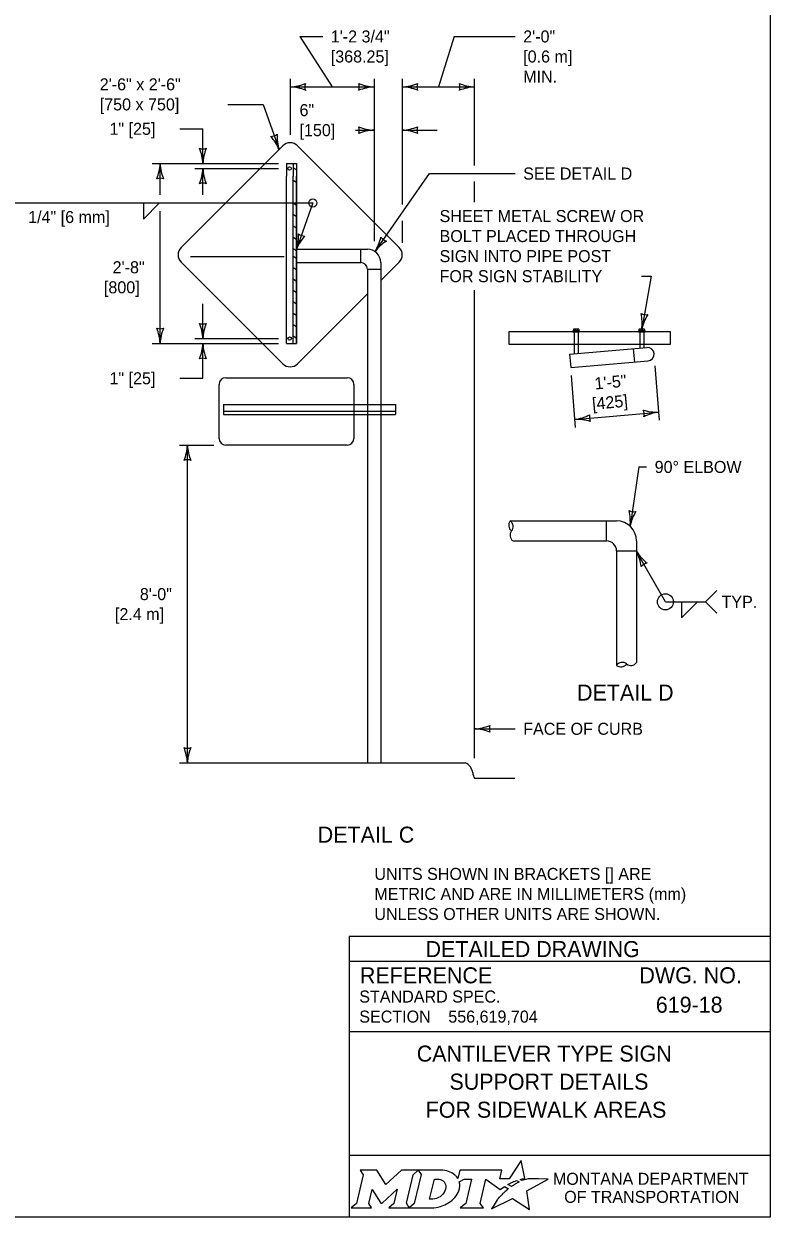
# Model space of a CAD drawing. Extents: x 49991.4 to 50021, y 49987.6 to 50011.4.
# Drawn here: x 50013.03 to 50016.75, y 49987.8 to 49993.75 of the extents above; entities that cross this region are included whole.
import ezdxf

# ---------------------------------------------------------------- set-up
doc = ezdxf.new("R2010")
doc.units = 0
for name, color, linetype in [('Default', 7, 'Continuous'), ('Level 1', 7, 'Continuous'), ('Level 2', 7, 'Continuous'), ('Level 3', 7, 'Continuous'), ('Level 4', 7, 'Continuous'), ('Level 5', 7, 'Continuous')]:
    doc.layers.add(name, color=color, linetype=linetype)

msp = doc.modelspace()

# ---------------------------------------------------------------- linework, layer by layer
at = {"layer": 'Default'}
for points in [[(50015.5126, 49987.9811), (50015.5023, 49987.9867), (50015.5139, 49987.9895), (50015.5255, 49987.9915), (50015.5081, 49988.0816), (50015.4486, 49987.9903), (50015.4013, 49987.9896), (50015.4116, 49988.0337), (50015.2024, 49988.0338), (50015.1923, 49987.9913), (50015.1865, 49987.9996)], [(50014.7056, 49988.0338), (50014.7197, 49988.0104), (50014.6862, 49987.8671), (50014.6605, 49987.8446), (50014.7621, 49987.8446), (50014.7486, 49987.8674), (50014.7648, 49987.9375), (50014.8085, 49987.8685), (50014.8138, 49987.8685), (50014.8889, 49987.938), (50014.8725, 49987.8669), (50014.8478, 49987.8449), (50014.9494, 49987.8449), (50014.9356, 49987.8682), (50014.9688, 49988.0106)], [(50014.9688, 49988.0106), (50014.9941, 49988.0338), (50014.9117, 49988.0338), (50014.8321, 49987.9608), (50014.7876, 49988.0335), (50014.7056, 49988.0338)], [(50015.1077, 49988.0338), (50014.9941, 49988.0338), (50015.0088, 49988.0109), (50014.9749, 49987.8671), (50014.9494, 49987.8449), (50015.06, 49987.8449)], [(50015.1317, 49987.9471), (50015.1305, 49987.939), (50015.1273, 49987.9297), (50015.1231, 49987.9215), (50015.1175, 49987.914), (50015.111, 49987.9071), (50015.1031, 49987.9008), (50015.0948, 49987.8961), (50015.0857, 49987.8922), (50015.0766, 49987.8899), (50015.0674, 49987.889), (50015.0515, 49987.889), (50015.0751, 49987.989), (50015.0911, 49987.989), (50015.0987, 49987.9884), (50015.1063, 49987.9865), (50015.1129, 49987.9835), (50015.119, 49987.9793), (50015.1238, 49987.9743), (50015.1275, 49987.9683), (50015.1302, 49987.9621), (50015.1318, 49987.9547), (50015.1318, 49987.9517), (50015.1317, 49987.9471)], [(50015.1991, 49987.9747), (50015.2237, 49987.9878), (50015.2606, 49987.9878), (50015.232, 49987.8673), (50015.2045, 49987.8446), (50015.3207, 49987.8446), (50015.3037, 49987.8675), (50015.3319, 49987.9877), (50015.4032, 49987.936), (50015.4243, 49987.9511), (50015.444, 49987.9402)], [(50015.3882, 49987.8843), (50015.3729, 49987.8599), (50015.3682, 49987.8524), (50015.3624, 49987.8438), (50015.3601, 49987.8395), (50015.4654, 49987.8926), (50015.5493, 49987.8375), (50015.5362, 49987.9302), (50015.6431, 49987.9886), (50015.5938, 49987.9894), (50015.5637, 49987.9898), (50015.5429, 49987.9901), (50015.5361, 49987.9886), (50015.5312, 49987.9874), (50015.5228, 49987.9851), (50015.5126, 49987.9811)], [(50015.4622, 49987.9535), (50015.4598, 49987.9518), (50015.4415, 49987.9614), (50015.4518, 49987.9671), (50015.4559, 49987.9693), (50015.4645, 49987.9733), (50015.4702, 49987.9759), (50015.4781, 49987.9789), (50015.4854, 49987.9816), (50015.4972, 49987.9742), (50015.4932, 49987.9721), (50015.4886, 49987.9696), (50015.4844, 49987.9674), (50015.4794, 49987.9645), (50015.4775, 49987.9634), (50015.4748, 49987.9618), (50015.4723, 49987.9604), (50015.47, 49987.9588), (50015.4674, 49987.957), (50015.4647, 49987.9552), (50015.4622, 49987.9535)], [(50015.4021, 49987.9004), (50015.4021, 49987.9004)], [(50015.1057, 49987.8522), (50015.1141, 49987.8548), (50015.1271, 49987.8602), (50015.1475, 49987.8712)]]:
    msp.add_lwpolyline(points, dxfattribs=at)
for centre, radius, start, end in [((50015.1308, 49987.9554), 0.0709, 339.53292, 15.85821), ((50015.0868, 49987.9727), 0.1183, 300.91025, 339.13831)]:
    msp.add_arc(centre, radius, start, end, dxfattribs=at)
for centre, major_axis, ratio, start_param, end_param in [((50015.1056, 49987.9864), (0.0834, -0.0037), 0.568097, 0.61298, 1.570796), ((50015.1612, 49987.9937), (0.0361, -0.0295), 0.469099, 1.225588, 1.570796), ((50015.3952, 49987.8923), (-0.00694, -0.00806), 0.008222, 0, 3.137361), ((50015.4119, 49987.9106), (-0.0098, -0.0102), 0.016458, 3.141593, 6.279097), ((50015.4329, 49987.9305), (-0.0112, -0.0097), 0.021651, 3.157348, 6.283185), ((50015.0603, 49987.9932), (0, 0.1484), 0.987302, 3.139398, 3.456847)]:
    msp.add_ellipse(centre, major_axis=major_axis, ratio=ratio, start_param=start_param, end_param=end_param, dxfattribs=at)
at = {"layer": 'Level 1'}
for p, q in [((50014.3194, 49993.1447), (50013.8116, 49992.6368)), ((50014.8998, 49992.6368), (50014.3919, 49993.1447)), ((50014.3366, 49993.0555), (50014.3865, 49993.0555)), ((50014.3366, 49993.0555), (50014.3366, 49992.9931)), ((50014.3698, 49993.0555), (50014.3698, 49992.9931)), ((50014.3849, 49993.0243), (50014.3713, 49993.0334)), ((50014.3865, 49993.0555), (50014.3865, 49992.9931)), ((50014.3865, 49993.0555), (50014.3865, 49992.1577)), ((50014.3366, 49992.5992), (50014.3366, 49992.9931)), ((50014.3366, 49992.983), (50014.3366, 49992.9931)), ((50014.3698, 49992.9682), (50014.3698, 49992.9931)), ((50014.3698, 49992.5992), (50014.3698, 49992.9682)), ((50014.3865, 49992.9604), (50014.3704, 49992.9715)), ((50014.3865, 49992.983), (50014.3865, 49992.9931)), ((50014.3865, 49992.5992), (50014.3865, 49992.983)), ((50014.3865, 49992.8468), (50014.3704, 49992.8577)), ((50014.3865, 49992.79), (50014.3704, 49992.8009)), ((50014.3865, 49992.7331), (50014.3704, 49992.744)), ((50014.3865, 49992.6762), (50014.3704, 49992.6872)), ((50014.3865, 49992.6193), (50014.3704, 49992.6303)), ((50014.3865, 49992.6283), (50014.7407, 49992.6283)), ((50014.7074, 49992.5618), (50014.7074, 49992.6283)), ((50013.8116, 49992.5642), (50014.3194, 49992.0564)), ((50014.3366, 49992.1577), (50014.3366, 49992.5992)), ((50014.3698, 49992.1577), (50014.3698, 49992.5992)), ((50014.3865, 49992.5815), (50014.3704, 49992.5925)), ((50014.3865, 49992.1577), (50014.3865, 49992.5992)), ((50014.3865, 49992.5618), (50014.7074, 49992.5618)), ((50014.8072, 49992.4716), (50014.8998, 49992.5642)), ((50014.8072, 49992.5618), (50014.8072, 49990.0653)), ((50014.3865, 49992.5246), (50014.3704, 49992.5355)), ((50014.7407, 49992.5285), (50014.7407, 49990.0653)), ((50014.7407, 49992.5285), (50014.8071, 49992.5285)), ((50014.3865, 49992.4677), (50014.3704, 49992.4786)), ((50014.3865, 49992.4109), (50014.3704, 49992.4218)), ((50014.3865, 49992.354), (50014.3704, 49992.3649)), ((50014.3919, 49992.0564), (50014.7407, 49992.4051)), ((50014.3865, 49992.2972), (50014.3704, 49992.3081)), ((50014.3865, 49992.2403), (50014.3704, 49992.2512)), ((50014.3865, 49992.1834), (50014.3704, 49992.1943)), ((50015.7685, 49992.2268), (50015.7685, 49992.2207)), ((50015.7936, 49992.2294), (50015.771, 49992.2294)), ((50015.7937, 49992.2294), (50015.771, 49992.2294)), ((50015.7777, 49992.2294), (50015.7777, 49992.2207)), ((50015.7871, 49992.2294), (50015.7871, 49992.2207)), ((50015.7962, 49992.2268), (50015.7962, 49992.2207)), ((50016.0956, 49992.2268), (50016.0956, 49992.2207)), ((50016.1208, 49992.2294), (50016.0979, 49992.2294)), ((50016.1211, 49992.2294), (50016.0986, 49992.2294)), ((50016.1048, 49992.2294), (50016.1048, 49992.2207)), ((50016.1141, 49992.2294), (50016.1141, 49992.2207)), ((50016.1233, 49992.2268), (50016.1233, 49992.2207)), ((50014.3366, 49992.1577), (50014.3865, 49992.1577)), ((50015.7494, 49992.1037), (50016.1355, 49992.1374)), ((50015.7725, 49992.1543), (50015.7725, 49992.1057)), ((50015.7925, 49992.1543), (50015.7925, 49992.1075)), ((50016.075, 49992.0654), (50016.0692, 49992.1316)), ((50016.0995, 49992.1543), (50016.0995, 49992.1343)), ((50016.1195, 49992.1543), (50016.1195, 49992.136)), ((50015.7494, 49992.1037), (50015.7553, 49992.0374)), ((50015.7553, 49992.0374), (50016.1411, 49992.0712)), ((50015.4532, 49991.2725), (50015.9839, 49991.2725)), ((50015.934, 49991.1727), (50015.934, 49991.2725)), ((50015.4673, 49991.1725), (50015.934, 49991.1727)), ((50015.9839, 49991.1228), (50015.9837, 49990.5516)), ((50015.9839, 49991.1228), (50016.0836, 49991.1229)), ((50016.0836, 49991.1727), (50016.0837, 49990.5658)), ((50013.8027, 49990.0653), (50015.1731, 49990.0653)), ((50015.1731, 49990.0653), (50015.2293, 49990.0653)), ((50015.2759, 49989.9882), (50015.4759, 49989.9882))]:
    msp.add_line(p, q, dxfattribs=at)
for points in [[(49999.3835, 49998.9992), (50016.7501, 49998.9992), (50016.7501, 49987.7988), (49999.3835, 49987.7988)], [(50016.2532, 49992.1543), (50016.2532, 49992.216), (50015.4457, 49992.216), (50015.4457, 49992.1543)], [(50015.7989, 49992.2158), (50015.7989, 49992.2205), (50015.7661, 49992.2205), (50015.7661, 49992.2158)], [(50016.126, 49992.2158), (50016.126, 49992.2205), (50016.0931, 49992.2205), (50016.0931, 49992.2158)]]:
    msp.add_lwpolyline(points, close=True, dxfattribs=at)
for centre in [(50014.353, 49993.031), (50014.353, 49992.1822)]:
    msp.add_circle(centre, 0.00843, dxfattribs=at)
for centre, radius, start, end in [((50014.3557, 49993.1084), 0.0513, 45.00008, 134.99993), ((50013.8478, 49992.6005), 0.0513, 134.99993, 225.00008), ((50014.7407, 49992.5618), 0.0665, 0, 90), ((50014.8635, 49992.6005), 0.0513, 314.99993, 45.00008), ((50014.7074, 49992.5285), 0.0333, 0, 90), ((50015.7711, 49992.2268), 0.00257, 90, 180), ((50015.7752, 49992.2268), 0.00257, 0, 90), ((50015.7804, 49992.2268), 0.00257, 90, 180), ((50015.7844, 49992.2268), 0.00257, 0, 90), ((50015.7896, 49992.2268), 0.00257, 90, 180), ((50015.7936, 49992.2268), 0.00257, 0, 90), ((50016.0982, 49992.2268), 0.00257, 97.71849, 180), ((50016.1023, 49992.2268), 0.00257, 360, 82.28151), ((50016.1074, 49992.2268), 0.00257, 97.71849, 180), ((50016.1115, 49992.2268), 0.00257, 0, 82.28151), ((50016.1167, 49992.2268), 0.00257, 97.71849, 180), ((50016.1207, 49992.2268), 0.00257, 0, 82.28151), ((50016.1383, 49992.1043), 0.0332, 274.91306, 94.91306), ((50014.3557, 49992.0927), 0.0513, 225.00007, 314.99993), ((50015.4816, 49991.2506), 0.0359, 142.47417, 231.88124), ((50015.4344, 49991.2442), 0.034, 320.09958, 55.51698), ((50015.9839, 49991.1727), 0.0998, 0, 90), ((50015.4866, 49991.2006), 0.034, 140.09958, 235.51698), ((50015.4816, 49991.2506), 0.0359, 232.45136, 233.33014), ((50015.934, 49991.1228), 0.0499, 0, 90), ((50016.012, 49990.5328), 0.034, 50.09958, 145.51698), ((50016.0556, 49990.585), 0.034, 230.09958, 325.51698), ((50015.2056, 49990.0091), 0.061, 5.91179, 67.14905)]:
    msp.add_arc(centre, radius, start, end, dxfattribs=at)
for centre, major_axis, ratio, start_param, end_param in [((50016.0061, 49990.5807), (-0.0223, -0.0291), 0.979506, 0, 1.560448), ((50015.3269, 49990.0217), (-0.0223, -0.0568), 0.999596, 5.190058, 5.66782)]:
    msp.add_ellipse(centre, major_axis=major_axis, ratio=ratio, start_param=start_param, end_param=end_param, dxfattribs=at)
at = {"layer": 'Level 3'}
for p, q in [((50014.4034, 49993.6897), (50014.5647, 49993.4377)), ((50014.4034, 49993.6897), (50014.5181, 49993.6897)), ((50015.1745, 49993.6897), (50015.0954, 49993.4377)), ((50015.1745, 49993.6897), (50015.4781, 49993.6897)), ((50014.3554, 49993.4777), (50014.3554, 49993.1997)), ((50014.3554, 49993.4377), (50014.7739, 49993.4377)), ((50014.7739, 49993.4777), (50014.7739, 49992.6683)), ((50014.9148, 49993.4777), (50014.9148, 49992.8506)), ((50014.9148, 49993.4377), (50015.276, 49993.4377)), ((50015.276, 49993.0459), (50015.276, 49993.4777)), ((50014.0441, 49993.3508), (50014.2205, 49993.3508)), ((50014.2205, 49993.3508), (50014.2999, 49993.1252)), ((50013.8051, 49993.2289), (50013.9204, 49993.2289)), ((50013.9204, 49993.0555), (50013.9204, 49993.2289)), ((50014.6817, 49993.2222), (50014.7739, 49993.2222)), ((50014.9148, 49993.2222), (50015.0882, 49993.2222)), ((50013.6668, 49993.0555), (50014.2966, 49993.0555)), ((50013.7068, 49992.8988), (50013.7068, 49993.0555)), ((50013.8804, 49993.031), (50014.2966, 49993.031)), ((50013.9204, 49992.8988), (50013.9204, 49993.031)), ((50014.7788, 49992.6162), (50015.0515, 49993.0059)), ((50015.0515, 49993.0059), (50015.2693, 49993.0059)), ((50015.2693, 49993.0059), (50015.4781, 49993.0059)), ((50015.276, 49992.8637), (50015.276, 49992.9659)), ((50012.9528, 49992.8588), (50014.1183, 49992.8588)), ((50013.6233, 49992.8588), (50013.6233, 49992.7788)), ((50013.6233, 49992.7788), (50013.7033, 49992.8588)), ((50014.1183, 49992.8588), (50014.2839, 49992.8588)), ((50014.2839, 49992.8588), (50014.4687, 49992.8588)), ((50014.4687, 49992.8588), (50014.3865, 49992.6283)), ((50013.7068, 49992.1577), (50013.7068, 49992.8188)), ((50014.9148, 49992.7706), (50014.9148, 49992.6605)), ((50016.1087, 49992.4937), (50016.1566, 49992.4937)), ((50016.1566, 49992.4937), (50016.1096, 49992.2298)), ((50015.276, 49990.0882), (50015.276, 49992.4237)), ((50013.9204, 49992.1822), (50013.9204, 49992.3556)), ((50013.6668, 49992.1577), (50014.2966, 49992.1577)), ((50013.8804, 49992.1822), (50014.2966, 49992.1822)), ((50013.9204, 49991.9843), (50013.9204, 49992.1577)), ((50016.1977, 49991.776), (50016.1766, 49992.047)), ((50013.8051, 49991.9843), (50013.9204, 49991.9843)), ((50015.7788, 49991.7393), (50015.7588, 49991.9975)), ((50015.7753, 49991.7791), (50016.1942, 49991.8158)), ((50013.8027, 49991.6507), (50013.9746, 49991.6507)), ((50013.8427, 49990.0653), (50013.8427, 49991.6507)), ((50016.0955, 49991.5417), (50016.0515, 49991.246)), ((50016.0955, 49991.5417), (50016.1341, 49991.5417)), ((50016.2277, 49990.8688), (50016.0837, 49991.1193)), ((50016.4277, 49990.8688), (50016.4843, 49990.9254)), ((50016.2277, 49990.8688), (50016.4277, 49990.8688)), ((50016.3077, 49990.8688), (50016.3077, 49990.7888)), ((50016.3077, 49990.7888), (50016.3877, 49990.8688)), ((50016.4277, 49990.8688), (50016.4843, 49990.8122)), ((50015.276, 49990.2353), (50015.4781, 49990.2353))]:
    msp.add_line(p, q, dxfattribs=at)
for centre, radius in [((50014.4687, 49992.8588), 0.0201), ((50016.2277, 49990.8688), 0.04)]:
    msp.add_circle(centre, radius, dxfattribs=at)
for centre, radius, start, end in [((50014.3439, 49993.6705), 0.233, 272.82731, 292.07716), ((50014.3463, 49993.2156), 0.2223, 67.45601, 87.63952), ((50014.4836, 49993.4377), 0.0548, 162.13882, 197.86118), ((50014.7831, 49993.6599), 0.2223, 247.45601, 267.63952), ((50014.6457, 49993.4377), 0.0548, 342.13882, 17.86118), ((50014.7854, 49993.205), 0.233, 92.82731, 112.07716), ((50014.9033, 49993.6705), 0.233, 272.82731, 292.07716), ((50014.9057, 49993.2156), 0.2223, 67.45601, 87.63952), ((50015.043, 49993.4377), 0.0548, 162.13882, 197.86118), ((50015.2851, 49993.6599), 0.2223, 247.45601, 267.63952), ((50015.1477, 49993.4377), 0.0548, 342.13882, 17.86118), ((50015.2874, 49993.205), 0.233, 92.82731, 112.07716), ((50014.2573, 49993.2461), 0.0548, 271.54113, 307.2635), ((50014.5125, 49993.1904), 0.2223, 176.85833, 197.04183), ((50014.7831, 49993.4443), 0.2223, 247.45601, 267.63952), ((50014.6457, 49993.2222), 0.0548, 342.13882, 17.86118), ((50014.7854, 49992.9895), 0.233, 92.82731, 112.07716), ((50014.9033, 49993.4549), 0.233, 272.82731, 292.07716), ((50014.9057, 49993.0001), 0.2223, 67.45601, 87.63952), ((50015.043, 49993.2222), 0.0548, 162.13882, 197.86118), ((50014.0842, 49993.0371), 0.233, 22.22963, 41.47948), ((50013.9204, 49993.1837), 0.0548, 252.13882, 287.86118), ((50013.6877, 49993.044), 0.233, 2.82731, 22.07716), ((50014.1425, 49993.0463), 0.2223, 157.45601, 177.63952), ((50013.4847, 49993.0647), 0.2223, 337.45601, 357.63952), ((50013.9395, 49993.067), 0.233, 182.82731, 202.07716), ((50013.6983, 49993.0402), 0.2223, 337.45601, 357.63952), ((50014.1531, 49993.0425), 0.233, 182.82731, 202.07716), ((50013.7068, 49992.9273), 0.0548, 72.13882, 107.86118), ((50013.9204, 49992.9028), 0.0548, 72.13882, 107.86118), ((50014.1644, 49992.6986), 0.233, 342.44053, 1.69038), ((50014.5915, 49992.5423), 0.2223, 137.06923, 157.25274), ((50014.4312, 49992.7485), 0.0548, 231.75204, 267.4744), ((50014.5816, 49992.7403), 0.233, 327.84304, 347.09289), ((50014.9556, 49992.4814), 0.2223, 122.47174, 142.65525), ((50014.8523, 49992.7213), 0.0548, 217.15455, 252.87691), ((50016.1321, 49992.3564), 0.0551, 242.04763, 277.76999), ((50015.877, 49992.259), 0.2344, 352.73612, 11.98597), ((50013.9204, 49992.3104), 0.0548, 252.13882, 287.86118), ((50013.6877, 49992.1707), 0.233, 2.82731, 22.07716), ((50014.1425, 49992.173), 0.2223, 157.45601, 177.63952), ((50016.328, 49992.1811), 0.2237, 147.36482, 167.54833), ((50013.7068, 49992.2859), 0.0548, 252.13882, 287.86118), ((50013.4741, 49992.1462), 0.233, 2.82731, 22.07716), ((50013.9289, 49992.1485), 0.2223, 157.45601, 177.63952), ((50013.6983, 49992.1669), 0.2223, 337.45601, 357.63952), ((50014.1531, 49992.1692), 0.233, 182.82731, 202.07716), ((50013.9204, 49992.0295), 0.0548, 72.13882, 107.86118), ((50015.7435, 49992.0099), 0.233, 277.84279, 297.09264), ((50015.7856, 49991.557), 0.2223, 72.47149, 92.655), ((50015.9031, 49991.7903), 0.0548, 167.1543, 202.87666), ((50016.1839, 49992.0379), 0.2223, 252.47149, 272.655), ((50016.0665, 49991.8046), 0.0548, 347.1543, 22.87666), ((50016.226, 49991.585), 0.233, 97.84279, 117.09264), ((50013.6206, 49991.6599), 0.2223, 337.45601, 357.63952), ((50014.0754, 49991.6622), 0.233, 182.82731, 202.07716), ((50013.8427, 49991.5225), 0.0548, 72.13882, 107.86118), ((50016.0704, 49991.3728), 0.0548, 243.67431, 279.39667), ((50015.8197, 49991.2689), 0.233, 354.3628, 13.61265), ((50016.2699, 49991.2042), 0.2223, 148.9915, 169.17501), ((50015.8866, 49991.0165), 0.2223, 7.35104, 27.53455), ((50016.2798, 49991.2452), 0.233, 212.72234, 231.97219), ((50016.1476, 49991.0081), 0.0548, 102.03385, 137.75621), ((50015.2645, 49990.468), 0.233, 272.82731, 292.07716), ((50015.2668, 49990.0132), 0.2223, 67.45601, 87.63952), ((50015.4042, 49990.2353), 0.0548, 162.13882, 197.86118), ((50013.8427, 49990.1935), 0.0548, 252.13882, 287.86118), ((50013.61, 49990.0538), 0.233, 2.82731, 22.07716), ((50014.0648, 49990.0561), 0.2223, 157.45601, 177.63952)]:
    msp.add_arc(centre, radius, start, end, dxfattribs=at)
at = {"layer": 'Level 4'}
for p, q in [((50015.7725, 49992.2158), (50015.7725, 49992.1543)), ((50015.7925, 49992.2158), (50015.7925, 49992.1543)), ((50016.0995, 49992.2158), (50016.0995, 49992.1543)), ((50016.1195, 49992.2158), (50016.1195, 49992.1543)), ((50014.0009, 49991.6844), (50014.0009, 49991.9536)), ((50014.0346, 49991.9872), (50014.6401, 49991.9872)), ((50014.6738, 49991.9536), (50014.6738, 49991.6844)), ((50014.0229, 49991.8541), (50014.0229, 49991.8041)), ((50014.0229, 49991.8541), (50014.8805, 49991.8541)), ((50014.8805, 49991.8541), (50014.8805, 49991.8041)), ((50014.0229, 49991.8209), (50014.8805, 49991.8209)), ((50014.0229, 49991.8041), (50014.8805, 49991.8041)), ((50014.6401, 49991.6507), (50014.0346, 49991.6507))]:
    msp.add_line(p, q, dxfattribs=at)
for centre, start, end in [((50014.0345, 49991.9536), 90, 180), ((50014.6401, 49991.9536), 0, 90), ((50014.6401, 49991.6844), 270, 0)]:
    msp.add_arc(centre, 0.0336, start, end, dxfattribs=at)
msp.add_ellipse((50014.0346, 49991.6844), major_axis=(-0.0337, 0), ratio=0.998923, start_param=0, end_param=1.570796, dxfattribs=at)
at = {"layer": 'Level 5'}
for p, q in [((50013.8575, 49992.5918), (50014.3255, 49992.5918)), ((50016.7501, 49989.1988), (50014.6501, 49989.1988)), ((50014.6501, 49989.1988), (50014.6501, 49987.7988)), ((50016.7501, 49989.0738), (50014.6501, 49989.0738)), ((50016.3862, 49988.8587), (50016.3862, 49988.8587)), ((50015.1444, 49988.7993), (50015.1444, 49988.7993)), ((50016.7501, 49988.7238), (50014.6501, 49988.7238)), ((50015.7001, 49988.4747), (50015.7001, 49988.4747)), ((50016.7501, 49988.1057), (50014.6501, 49988.1057))]:
    msp.add_line(p, q, dxfattribs=at)

# ---------------------------------------------------------------- texts
at = {"layer": 'Default'}
for s, p in [('MONTANA DEPARTMENT', (50015.6663, 49987.96)), ('OF TRANSPORTATION', (50015.7225, 49987.87))]:
    msp.add_text(s, height=0.06, dxfattribs=at).set_placement(p)
at = {"layer": 'Level 2'}
for s, height, p in [('1\'-2 3/4"', 0.06, (50014.5581, 49993.6597)), ('2\'-0"', 0.06, (50015.5181, 49993.6597)), ('[368.25]', 0.06, (50014.5581, 49993.5597)), ('[0.6 m]', 0.06, (50015.5181, 49993.5597)), ('MIN.', 0.06, (50015.5181, 49993.4597)), ('2\'-6" x 2\'-6"', 0.06, (50013.4055, 49993.4208)), ('[750 x 750]', 0.06, (50013.4055, 49993.3208)), ('6"', 0.06, (50014.4022, 49993.2922)), ('1" [25]', 0.06, (50013.454, 49993.1989)), ('[150]', 0.06, (50014.4022, 49993.1922)), ('SEE DETAIL D', 0.06, (50015.5181, 49992.9759)), ('1/4" [6 mm]', 0.06, (50013.0483, 49992.7588)), ('SHEET METAL SCREW OR', 0.06, (50015.1009, 49992.7637)), ('BOLT PLACED THROUGH', 0.06, (50015.1009, 49992.6637)), ('SIGN INTO PIPE POST', 0.06, (50015.1009, 49992.5637)), ('2\'-8"', 0.06, (50013.4699, 49992.5082)), ('FOR SIGN STABILITY', 0.06, (50015.1009, 49992.4637)), ('[800]', 0.06, (50013.4264, 49992.4082)), ('1" [25]', 0.06, (50013.454, 49991.9543)), ('90° ELBOW', 0.06, (50016.1741, 49991.5117)), ('8\'-0"', 0.06, (50013.6057, 49990.8774)), ('TYP.', 0.06, (50016.5077, 49990.8388)), ('[2.4 m]', 0.06, (50013.4813, 49990.7774)), ('DETAIL D', 0.08, (50015.7869, 49990.3761)), ('FACE OF CURB', 0.06, (50015.5181, 49990.2053)), ('DETAIL C', 0.08, (50014.4931, 49989.6672)), ('UNITS SHOWN IN BRACKETS [] ARE ', 0.06, (50014.7757, 49989.4813)), ('METRIC AND ARE IN MILLIMETERS (mm) ', 0.06, (50014.7757, 49989.3813)), ('UNLESS OTHER UNITS ARE SHOWN.', 0.06, (50014.7757, 49989.2813)), ('619-18', 0.08, (50016.1798, 49988.8187)), ('556,619,704', 0.06, (50015.1444, 49988.7693)), ('CANTILEVER TYPE SIGN', 0.08, (50014.987, 49988.5747)), ('SUPPORT DETAILS', 0.08, (50015.1504, 49988.4347)), ('FOR SIDEWALK AREAS', 0.08, (50015.0316, 49988.2947))]:
    msp.add_text(s, height=height, dxfattribs=at).set_placement(p)
for s, p in [('1\'-5"', (50015.877, 49991.9279)), ('[425]', (50015.8646, 49991.8264))]:
    msp.add_text(s, height=0.06, rotation=5.36424, dxfattribs=at).set_placement(p)
at = {"layer": 'Level 5'}
for s, height, p in [('DETAILED DRAWING', 0.0799, (50015.0311, 49989.0963)), ('REFERENCE', 0.08, (50014.7037, 49988.9654)), ('DWG. NO.', 0.08, (50016.0979, 49988.9654)), ('STANDARD SPEC.', 0.06, (50014.7004, 49988.8694)), ('SECTION', 0.06, (50014.7004, 49988.7694))]:
    msp.add_text(s, height=height, dxfattribs=at).set_placement(p)

doc.saveas('drawing.dxf')
